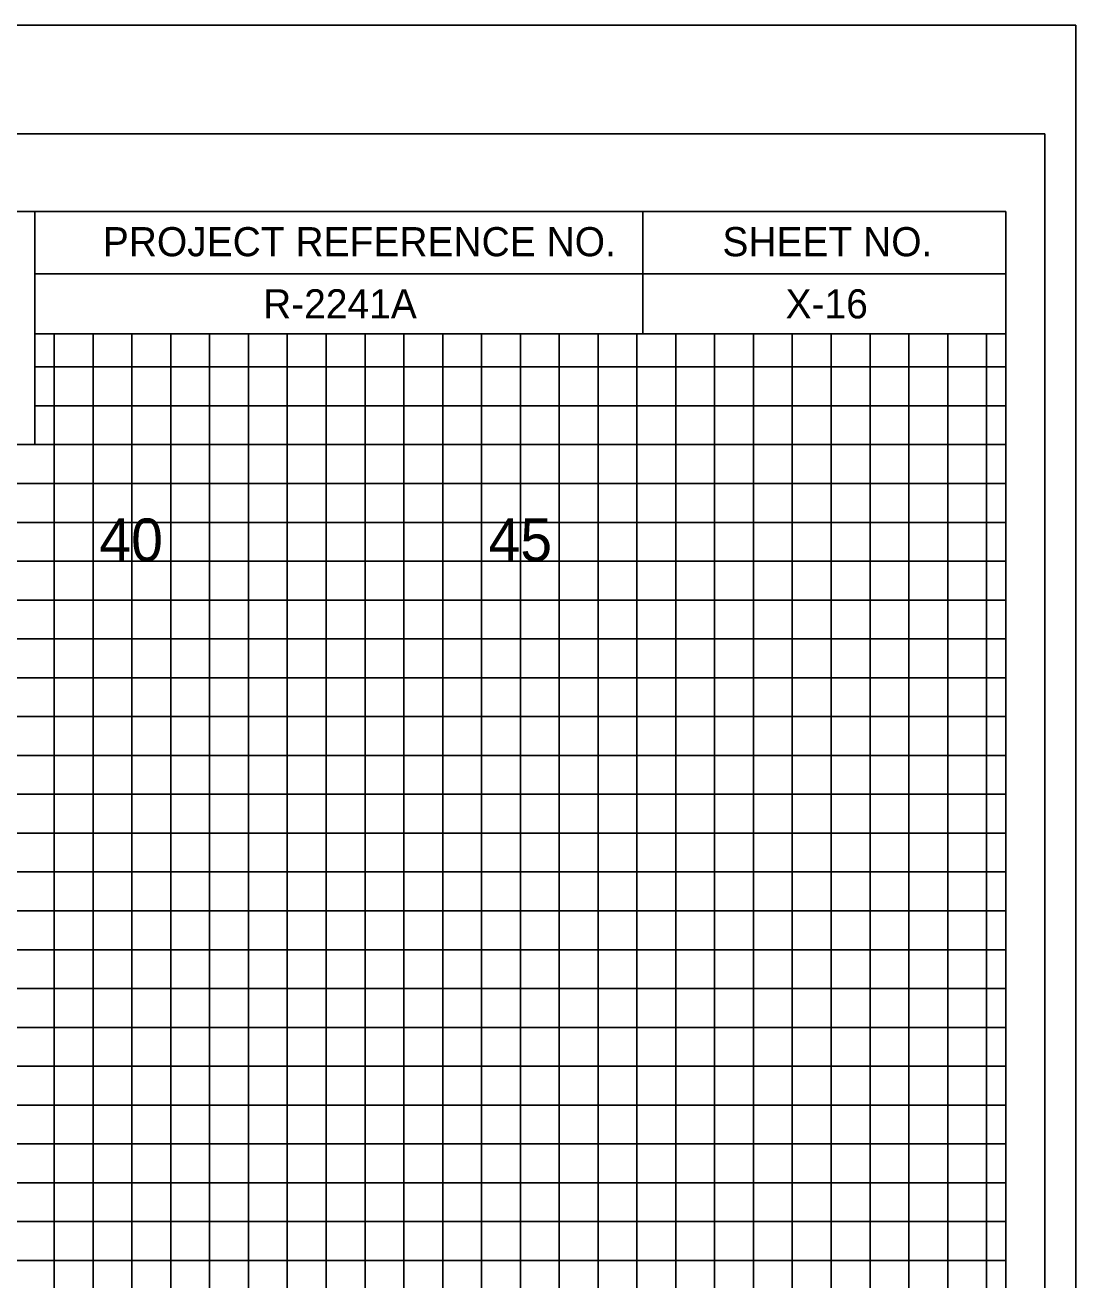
# Model space of a CAD drawing. Extents: x -4 to 103, y -2 to 6583.
# Drawn here: x 89.88 to 103.4, y 1113.62 to 1129.78 of the extents above; entities that cross this region are included whole.
import ezdxf

# ---------------------------------------------------------------- set-up
doc = ezdxf.new("R2010")
doc.units = 0
for name, color, linetype in [('Prop XS Offset Labels', 7, 'Continuous'), ('Prop XS Project Number', 7, 'Continuous'), ('Prop XS Sheet Number', 7, 'Continuous'), ('Sheet Cross Section CELL', 7, 'Continuous'), ('Sheet Cross Section Grid Major CELL', 7, 'Continuous'), ('Sheet Cross Section Grid Middle CELL', 7, 'Continuous'), ('Sheet Cutting Line CELL', 7, 'Continuous'), ('Sheet DOT Grid CELL', 7, 'Continuous'), ('Sheet Plot Border Inside CELL', 7, 'Continuous'), ('Sheet Plot Border Outside CELL', 7, 'Continuous')]:
    doc.layers.add(name, color=color, linetype=linetype)

msp = doc.modelspace()

# ---------------------------------------------------------------- linework, layer by layer
at = {"layer": 'Sheet Cross Section CELL'}
for p, q in [((90, 1127.375), (102.5, 1127.375)), ((90, 1127.375), (102.5, 1127.375)), ((97.825, 1125.8), (97.825, 1127.375)), ((101.875, 1127.375), (101.875, 1127.375)), ((102.5, 1127.375), (102.5, 1127.375)), ((102.5, 1125.8), (102.5, 1127.375)), ((102.5, 1127.375), (102.5, 1127.375)), ((102.5, 1127.375), (102.5, 1127.375)), ((102.5, 1125.8), (102.5, 1127.375)), ((90, 1126.575), (102.5, 1126.575)), ((90, 1125.8), (102.5, 1125.8)), ((99.4, 1125.8), (99.4, 1125.8)), ((99.4, 1125.8), (99.4, 1125.8))]:
    msp.add_line(p, q, dxfattribs=at)
for points in [[(102.5, 1127.375), (0, 1127.375), (0, 1062.375), (102.5, 1062.375)], [(83.75, 1127.375), (90, 1127.375), (90, 1124.375), (83.75, 1124.375)]]:
    msp.add_lwpolyline(points, close=True, dxfattribs=at)
at = {"layer": 'Sheet Cross Section Grid Major CELL'}
for points in [[(91.25, 1062.375), (91.25, 1125.8), (93.75, 1125.8), (93.75, 1062.375)], [(96.25, 1062.375), (96.25, 1125.8), (98.75, 1125.8), (98.75, 1062.375)], [(101.25, 1062.375), (101.25, 1125.8)], [(90, 1124.875), (102.5, 1124.875)], [(0, 1119.875), (102.5, 1119.875), (102.5, 1122.375), (0, 1122.375)], [(0, 1114.875), (102.5, 1114.875), (102.5, 1117.375), (0, 1117.375)]]:
    msp.add_lwpolyline(points, dxfattribs=at)
at = {"layer": 'Sheet Cross Section Grid Middle CELL'}
for points in [[(90.25, 1062.375), (90.25, 1125.8), (90.75, 1125.8), (90.75, 1062.375)], [(91.75, 1062.375), (91.75, 1125.8), (92.25, 1125.8), (92.25, 1062.375)], [(92.75, 1062.375), (92.75, 1125.8), (93.25, 1125.8), (93.25, 1062.375)], [(94.25, 1062.375), (94.25, 1125.8), (94.75, 1125.8), (94.75, 1062.375)], [(95.25, 1062.375), (95.25, 1125.8), (95.75, 1125.8), (95.75, 1062.375)], [(96.75, 1062.375), (96.75, 1125.8), (97.25, 1125.8), (97.25, 1062.375)], [(97.75, 1062.375), (97.75, 1125.8), (98.25, 1125.8), (98.25, 1062.375)], [(99.25, 1062.375), (99.25, 1125.8), (99.75, 1125.8), (99.75, 1062.375)], [(100.25, 1062.375), (100.25, 1125.8)], [(100.25, 1125.8), (100.75, 1125.8), (100.75, 1062.375), (101.75, 1062.375), (101.75, 1125.8), (102.25, 1125.8), (102.25, 1062.375)], [(102.5, 1124.375), (102.5, 1125.375), (90, 1125.375)], [(0, 1123.875), (102.5, 1123.875), (102.5, 1124.375), (0, 1124.375)], [(0, 1122.875), (102.5, 1122.875), (102.5, 1123.375), (0, 1123.375)], [(0, 1121.375), (102.5, 1121.375), (102.5, 1121.875), (0, 1121.875)], [(0, 1120.375), (102.5, 1120.375), (102.5, 1120.875), (0, 1120.875)], [(0, 1118.875), (102.5, 1118.875), (102.5, 1119.375), (0, 1119.375)], [(0, 1117.875), (102.5, 1117.875), (102.5, 1118.375), (0, 1118.375)], [(0, 1116.375), (102.5, 1116.375), (102.5, 1116.875), (0, 1116.875)], [(0, 1115.375), (102.5, 1115.375), (102.5, 1115.875), (0, 1115.875)], [(0, 1113.875), (102.5, 1113.875), (102.5, 1114.375), (0, 1114.375)]]:
    msp.add_lwpolyline(points, dxfattribs=at)
at = {"layer": 'Sheet Cutting Line CELL'}
msp.add_line((-3.5, 1129.775), (103.4, 1129.775), dxfattribs=at)
at = {"layer": 'Sheet DOT Grid CELL'}
for p, q in [((91.25, 1062.375), (91.25, 1125.8)), ((93.75, 1062.375), (93.75, 1125.8)), ((96.25, 1062.375), (96.25, 1125.8)), ((98.75, 1062.375), (98.75, 1125.8)), ((101.25, 1062.375), (101.25, 1125.8)), ((90, 1124.875), (102.5, 1124.875)), ((0, 1122.375), (102.5, 1122.375)), ((0, 1119.875), (102.5, 1119.875)), ((0, 1117.375), (102.5, 1117.375)), ((0, 1114.875), (102.5, 1114.875))]:
    msp.add_line(p, q, dxfattribs=at)
at = {"layer": 'Sheet Plot Border Inside CELL'}
msp.add_lwpolyline([(103, 1128.375), (-2.8, 1128.375), (-2.8, 1061.375), (103, 1061.375)], close=True, dxfattribs=at)
at = {"layer": 'Sheet Plot Border Outside CELL'}
msp.add_lwpolyline([(103.4, 1129.775), (-3.5, 1129.775), (-3.5, 1059.95), (103.4, 1059.95)], close=True, dxfattribs=at)

# ---------------------------------------------------------------- texts
at = {"layer": 'Prop XS Offset Labels'}
for s, p in [('40', (90.831, 1122.875)), ('45', (95.84, 1122.875))]:
    msp.add_text(s, height=0.55, dxfattribs=at).set_placement(p)
at = {"layer": 'Prop XS Project Number'}
msp.add_text('R-2241A', height=0.375, dxfattribs=at).set_placement((92.938, 1126))
at = {"layer": 'Prop XS Sheet Number'}
msp.add_text('X-16', height=0.375, dxfattribs=at).set_placement((99.663, 1126))
at = {"layer": 'Sheet Cross Section CELL'}
for s, p in [('PROJECT REFERENCE NO.', (90.875, 1126.8)), ('SHEET NO.', (98.85, 1126.8))]:
    msp.add_text(s, height=0.375, dxfattribs=at).set_placement(p)

doc.saveas('drawing.dxf')
